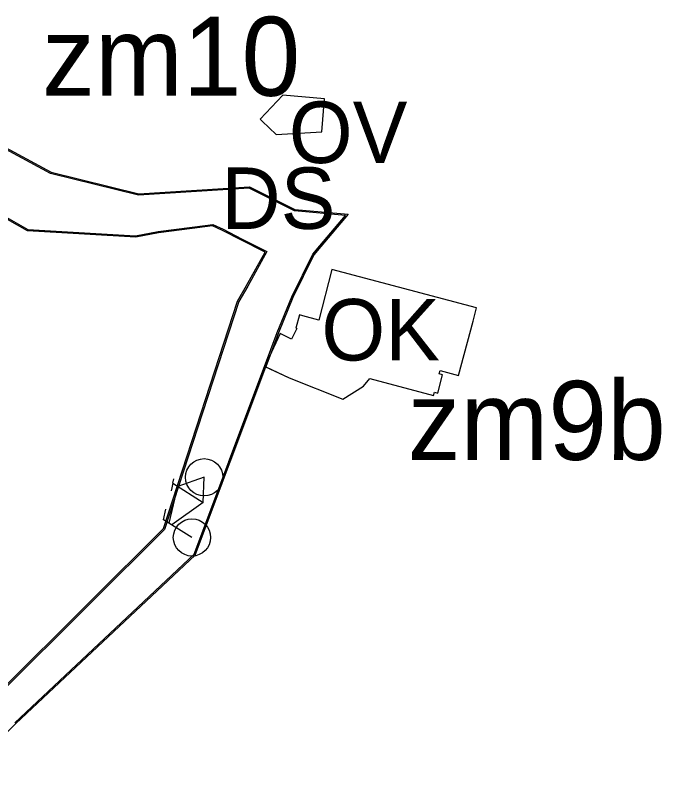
# Model space of a CAD drawing. Extents: x -555070 to -553076, y -1186731 to -1182766.
# Drawn here: x -554565.4 to -554418.1, y -1184653.9 to -1184476.2 of the extents above; entities that cross this region are included whole.
import ezdxf

# ---------------------------------------------------------------- set-up
doc = ezdxf.new("R2010")
doc.units = 0
for name, color, linetype in [('CYKLISTI_stav', 7, 'Continuous'), ('HRANICE_ZMENY_DO_KOO', 7, 'Continuous'), ('Level 10', 7, 'Continuous'), ('Level 13', 7, 'Continuous'), ('Level 59', 7, 'Continuous'), ('OBRYS_PLOCH', 7, 'Continuous'), ('stav_DS', 7, 'Continuous'), ('stav_OK', 7, 'Continuous'), ('stav_OV', 7, 'Continuous')]:
    doc.layers.add(name, color=color, linetype=linetype)

msp = doc.modelspace()

# ---------------------------------------------------------------- linework, layer by layer
at = {"layer": 'CYKLISTI_stav'}
for p, q in [((-554529.54, -1184582.69), (-554529.31, -1184581.72)), ((-554522.4, -1184581.37), (-554528.39, -1184583.44)), ((-554522.63, -1184587.11), (-554522.4, -1184581.37)), ((-554530.4, -1184591.85), (-554528.39, -1184583.44)), ((-554529.54, -1184582.69), (-554529.93, -1184584.47)), ((-554529.54, -1184582.69), (-554522.63, -1184587.11)), ((-554531.67, -1184591.05), (-554531.13, -1184588.67)), ((-554522.63, -1184587.11), (-554529.79, -1184592.22)), ((-554525.19, -1184595.09), (-554531.67, -1184591.05))]:
    msp.add_line(p, q, dxfattribs=at)
for centre in [(-554522.4, -1184581.38), (-554525.19, -1184595.09)]:
    msp.add_circle(centre, 4.25, dxfattribs=at)
at = {"layer": 'HRANICE_ZMENY_DO_KOO'}
for p, q in [((-554504.44, -1184494.32), (-554509.62, -1184499.78)), ((-554494.94, -1184495.16), (-554504.44, -1184494.32)), ((-554587.06, -1184495.79), (-554557.31, -1184511.89)), ((-554495.6, -1184502.63), (-554494.94, -1184495.16)), ((-554509.62, -1184499.78), (-554509.18, -1184500.21)), ((-554509.18, -1184500.21), (-554506.01, -1184503.24)), ((-554506.01, -1184503.24), (-554495.6, -1184502.63)), ((-554562.72, -1184525.2), (-554588.94, -1184510.3)), ((-554557.31, -1184511.89), (-554537.33, -1184516.78)), ((-554537.33, -1184516.78), (-554512.05, -1184515.19)), ((-554512.05, -1184515.19), (-554501.74, -1184520.35)), ((-554501.74, -1184520.35), (-554489.54, -1184521.46)), ((-554489.54, -1184521.46), (-554495.78, -1184528.8)), ((-554525.15, -1184524.68), (-554532.83, -1184525.68)), ((-554520.48, -1184524.08), (-554525.15, -1184524.68)), ((-554525.15, -1184524.68), (-554525.15, -1184524.68)), ((-554518.22, -1184525.13), (-554520.48, -1184524.08)), ((-554538.01, -1184526.66), (-554562.72, -1184525.2)), ((-554532.83, -1184525.68), (-554538.01, -1184526.66)), ((-554514.04, -1184527.3), (-554518.22, -1184525.13)), ((-554508.49, -1184530.08), (-554514.04, -1184527.3)), ((-554512.72, -1184537.7), (-554508.49, -1184530.08)), ((-554495.78, -1184528.8), (-554497.37, -1184530.68)), ((-554497.37, -1184530.68), (-554502.17, -1184540.4)), ((-554460.33, -1184542.77), (-554493.28, -1184534.02)), ((-554514.81, -1184541.24), (-554512.72, -1184537.7)), ((-554502.17, -1184540.4), (-554505.44, -1184548.5)), ((-554524.15, -1184569.93), (-554514.81, -1184541.24)), ((-554500.65, -1184544.34), (-554501.53, -1184547.4)), ((-554461.09, -1184545.8), (-554460.33, -1184542.77)), ((-554501.53, -1184547.4), (-554501.31, -1184547.46)), ((-554505.44, -1184548.5), (-554508.33, -1184556.21)), ((-554505.11, -1184548.62), (-554507.18, -1184553.14)), ((-554507.18, -1184553.14), (-554508.33, -1184556.21)), ((-554516.47, -1184577.89), (-554508.33, -1184556.21)), ((-554508.33, -1184556.21), (-554508.34, -1184556.23)), ((-554468.82, -1184557.84), (-554468.61, -1184557.07)), ((-554468.04, -1184558.05), (-554468.82, -1184557.84)), ((-554531.68, -1184593.08), (-554524.15, -1184569.93)), ((-554524.15, -1184569.93), (-554524.15, -1184569.93)), ((-554524.42, -1184599.09), (-554516.47, -1184577.89)), ((-554516.47, -1184577.89), (-554516.47, -1184577.89)), ((-554548.54, -1184609.85), (-554531.68, -1184593.08)), ((-554565.38, -1184637.51), (-554524.42, -1184599.09)), ((-554548.54, -1184609.85), (-554569.7, -1184630.88)), ((-554581.82, -1184653.86), (-554565.38, -1184637.51))]:
    msp.add_line(p, q, dxfattribs=at)
for points in [[(-554493.28, -1184534.02), (-554496.29, -1184545.6), (-554499.87, -1184544.56), (-554500.65, -1184544.34)], [(-554468.61, -1184557.07), (-554464.39, -1184558.17), (-554461.09, -1184545.8)], [(-554501.31, -1184547.46), (-554502.51, -1184549.89), (-554505.11, -1184548.62)], [(-554508.34, -1184556.23), (-554503.03, -1184558.71), (-554490.82, -1184563.58), (-554486.05, -1184560.65), (-554484.65, -1184558.85), (-554470.11, -1184562.71), (-554469.92, -1184562.02), (-554469.15, -1184562.23), (-554468.04, -1184558.05)]]:
    msp.add_lwpolyline(points, dxfattribs=at)
at = {"layer": 'Level 13'}
for p, q in [((-554504.44, -1184494.32), (-554509.62, -1184499.78)), ((-554494.94, -1184495.16), (-554504.44, -1184494.32)), ((-554495.6, -1184502.63), (-554494.94, -1184495.16)), ((-554509.62, -1184499.78), (-554509.18, -1184500.21)), ((-554509.18, -1184500.21), (-554506.01, -1184503.24)), ((-554506.01, -1184503.24), (-554495.6, -1184502.63))]:
    msp.add_line(p, q, dxfattribs=at)
at = {"layer": 'OBRYS_PLOCH'}
for p, q in [((-554504.44, -1184494.32), (-554509.62, -1184499.78)), ((-554494.94, -1184495.16), (-554504.44, -1184494.32)), ((-554557.42, -1184512.17), (-554587.16, -1184496.08)), ((-554557.42, -1184512.17), (-554587.16, -1184496.08)), ((-554495.6, -1184502.63), (-554494.94, -1184495.16)), ((-554509.62, -1184499.78), (-554509.18, -1184500.21)), ((-554509.18, -1184500.21), (-554506.01, -1184503.24)), ((-554506.01, -1184503.24), (-554495.6, -1184502.63)), ((-554588.8, -1184510.03), (-554562.63, -1184524.9)), ((-554588.8, -1184510.03), (-554562.63, -1184524.9)), ((-554537.36, -1184517.08), (-554557.42, -1184512.17)), ((-554537.36, -1184517.08), (-554557.42, -1184512.17)), ((-554512.11, -1184515.49), (-554537.36, -1184517.08)), ((-554512.11, -1184515.49), (-554537.36, -1184517.08)), ((-554501.82, -1184520.64), (-554512.11, -1184515.49)), ((-554501.82, -1184520.64), (-554512.11, -1184515.49)), ((-554490.14, -1184521.71), (-554501.82, -1184520.64)), ((-554490.14, -1184521.71), (-554501.82, -1184520.64)), ((-554496.01, -1184528.61), (-554490.14, -1184521.71)), ((-554496.01, -1184528.61), (-554490.14, -1184521.71)), ((-554532.88, -1184525.38), (-554525.17, -1184524.38)), ((-554532.88, -1184525.38), (-554525.17, -1184524.38)), ((-554525.17, -1184524.38), (-554520.43, -1184523.77)), ((-554525.17, -1184524.38), (-554520.43, -1184523.77)), ((-554525.17, -1184524.38), (-554525.17, -1184524.38)), ((-554525.17, -1184524.38), (-554525.17, -1184524.38)), ((-554520.43, -1184523.77), (-554518.09, -1184524.86)), ((-554520.43, -1184523.77), (-554518.09, -1184524.86)), ((-554518.09, -1184524.86), (-554513.9, -1184527.03)), ((-554518.09, -1184524.86), (-554513.9, -1184527.03)), ((-554513.9, -1184527.03), (-554508.08, -1184529.95)), ((-554513.9, -1184527.03), (-554508.08, -1184529.95)), ((-554508.08, -1184529.95), (-554512.46, -1184537.85)), ((-554508.08, -1184529.95), (-554512.46, -1184537.85)), ((-554497.62, -1184530.51), (-554496.01, -1184528.61)), ((-554497.62, -1184530.51), (-554496.01, -1184528.61)), ((-554502.44, -1184540.28), (-554497.62, -1184530.51)), ((-554502.44, -1184540.28), (-554497.62, -1184530.51)), ((-554512.46, -1184537.85), (-554514.53, -1184541.36)), ((-554512.46, -1184537.85), (-554514.53, -1184541.36)), ((-554505.72, -1184548.39), (-554502.44, -1184540.28)), ((-554505.72, -1184548.39), (-554502.44, -1184540.28)), ((-554514.53, -1184541.36), (-554523.93, -1184570.22)), ((-554514.53, -1184541.36), (-554523.93, -1184570.22)), ((-554508.61, -1184556.1), (-554505.72, -1184548.39)), ((-554508.61, -1184556.1), (-554505.72, -1184548.39)), ((-554516.75, -1184577.78), (-554508.61, -1184556.1)), ((-554516.75, -1184577.78), (-554508.61, -1184556.1)), ((-554523.93, -1184570.22), (-554531.42, -1184593.24)), ((-554523.93, -1184570.22), (-554531.42, -1184593.24)), ((-554523.93, -1184570.22), (-554523.93, -1184570.22)), ((-554523.93, -1184570.22), (-554523.93, -1184570.22)), ((-554524.68, -1184598.92), (-554516.77, -1184577.83)), ((-554524.68, -1184598.92), (-554516.77, -1184577.83)), ((-554516.77, -1184577.83), (-554516.75, -1184577.78)), ((-554516.77, -1184577.83), (-554516.75, -1184577.78)), ((-554516.77, -1184577.83), (-554516.77, -1184577.83)), ((-554516.77, -1184577.83), (-554516.77, -1184577.83)), ((-554531.42, -1184593.24), (-554548.33, -1184610.06)), ((-554531.42, -1184593.24), (-554548.33, -1184610.06)), ((-554565.59, -1184637.29), (-554524.68, -1184598.92)), ((-554565.59, -1184637.29), (-554524.68, -1184598.92)), ((-554548.33, -1184610.06), (-554569.5, -1184631.1)), ((-554548.33, -1184610.06), (-554569.5, -1184631.1))]:
    msp.add_line(p, q, dxfattribs=at)
msp.add_lwpolyline([(-554562.63, -1184524.9), (-554538.03, -1184526.36), (-554532.88, -1184525.38)], dxfattribs=at)
msp.add_lwpolyline([(-554562.63, -1184524.9), (-554538.03, -1184526.36), (-554532.88, -1184525.38)], dxfattribs=at)
msp.add_lwpolyline([(-554490.82, -1184563.58), (-554486.05, -1184560.65), (-554484.65, -1184558.85), (-554470.11, -1184562.71), (-554469.92, -1184562.02), (-554469.15, -1184562.23), (-554468.04, -1184558.05), (-554468.82, -1184557.84), (-554468.61, -1184557.07), (-554464.39, -1184558.17), (-554461.09, -1184545.8), (-554460.33, -1184542.77), (-554493.28, -1184534.02), (-554496.29, -1184545.6), (-554499.87, -1184544.56), (-554500.65, -1184544.34), (-554501.53, -1184547.4), (-554501.31, -1184547.46), (-554502.51, -1184549.89), (-554505.11, -1184548.62), (-554508.55, -1184556.13), (-554503.03, -1184558.71)], close=True, dxfattribs=at)
at = {"layer": 'stav_DS'}
for p, q in [((-554557.42, -1184512.17), (-554587.16, -1184496.08)), ((-554588.8, -1184510.03), (-554562.63, -1184524.9)), ((-554537.36, -1184517.08), (-554557.42, -1184512.17)), ((-554512.11, -1184515.49), (-554537.36, -1184517.08)), ((-554501.82, -1184520.64), (-554512.11, -1184515.49)), ((-554490.14, -1184521.71), (-554501.82, -1184520.64)), ((-554496.01, -1184528.61), (-554490.14, -1184521.71)), ((-554532.88, -1184525.38), (-554525.17, -1184524.38)), ((-554525.17, -1184524.38), (-554520.43, -1184523.77)), ((-554525.17, -1184524.38), (-554525.17, -1184524.38)), ((-554520.43, -1184523.77), (-554518.09, -1184524.86)), ((-554518.09, -1184524.86), (-554513.9, -1184527.03)), ((-554513.9, -1184527.03), (-554508.08, -1184529.95)), ((-554508.08, -1184529.95), (-554512.46, -1184537.85)), ((-554497.62, -1184530.51), (-554496.01, -1184528.61)), ((-554502.44, -1184540.28), (-554497.62, -1184530.51)), ((-554512.46, -1184537.85), (-554514.53, -1184541.36)), ((-554505.72, -1184548.39), (-554502.44, -1184540.28)), ((-554514.53, -1184541.36), (-554523.93, -1184570.22)), ((-554508.61, -1184556.1), (-554505.72, -1184548.39)), ((-554516.75, -1184577.78), (-554508.61, -1184556.1)), ((-554523.93, -1184570.22), (-554531.42, -1184593.24)), ((-554523.93, -1184570.22), (-554523.93, -1184570.22)), ((-554524.68, -1184598.92), (-554516.77, -1184577.83)), ((-554516.77, -1184577.83), (-554516.75, -1184577.78)), ((-554516.77, -1184577.83), (-554516.77, -1184577.83)), ((-554531.42, -1184593.24), (-554548.33, -1184610.06)), ((-554565.59, -1184637.29), (-554524.68, -1184598.92)), ((-554548.33, -1184610.06), (-554569.5, -1184631.1))]:
    msp.add_line(p, q, dxfattribs=at)
msp.add_lwpolyline([(-554562.63, -1184524.9), (-554538.03, -1184526.36), (-554532.88, -1184525.38)], dxfattribs=at)
at = {"layer": 'stav_OK'}
msp.add_lwpolyline([(-554490.82, -1184563.58), (-554486.05, -1184560.65), (-554484.65, -1184558.85), (-554470.11, -1184562.71), (-554469.92, -1184562.02), (-554469.15, -1184562.23), (-554468.04, -1184558.05), (-554468.82, -1184557.84), (-554468.61, -1184557.07), (-554464.39, -1184558.17), (-554461.09, -1184545.8), (-554460.33, -1184542.77), (-554493.28, -1184534.02), (-554496.29, -1184545.6), (-554499.87, -1184544.56), (-554500.65, -1184544.34), (-554501.53, -1184547.4), (-554501.31, -1184547.46), (-554502.51, -1184549.89), (-554505.11, -1184548.62), (-554508.55, -1184556.13), (-554503.03, -1184558.71)], close=True, dxfattribs=at)
at = {"layer": 'stav_OV'}
for p, q in [((-554504.44, -1184494.32), (-554509.62, -1184499.78)), ((-554494.94, -1184495.16), (-554504.44, -1184494.32)), ((-554495.6, -1184502.63), (-554494.94, -1184495.16)), ((-554509.62, -1184499.78), (-554509.18, -1184500.21)), ((-554509.18, -1184500.21), (-554506.01, -1184503.24)), ((-554506.01, -1184503.24), (-554495.6, -1184502.63))]:
    msp.add_line(p, q, dxfattribs=at)

# ---------------------------------------------------------------- texts
at = {"layer": 'Level 10'}
for s, p in [('zm10', (-554559.35, -1184494.45)), ('zm9b', (-554476, -1184577.42))]:
    msp.add_text(s, height=18, dxfattribs=at).set_placement(p)
at = {"layer": 'Level 59'}
for s, p in [('OV', (-554503.1, -1184509.77)), ('DS', (-554518.48, -1184524.78)), ('OK', (-554495.68, -1184554.76))]:
    msp.add_text(s, height=14, dxfattribs=at).set_placement(p)

doc.saveas('drawing.dxf')
